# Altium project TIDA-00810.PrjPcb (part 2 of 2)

## Sheet TIDA-00810_ADC1.SchDoc: ADC1
size 431 x 279 mm; Date: Not shown in title block; ApprovedBy: Not shown in title block; CheckedBy: Not shown in title block; Author: Not shown in title block; CompanyName: Not shown in title block; DrawnBy: Sreenivasa; Engineer: Not shown in title block; Organization: Not shown in title block; Address1: Not shown in title block; Address2: Not shown in title block; Address3: Not shown in title block; Address4: Not shown in title block; DocumentNumber: 1; Revision: Use project parameter SCH_Rev; SheetNumber: 7; SheetTotal: 10; PageSetup: Record=PageOptions¦CenterHorizontal=True¦CenterVertical=True¦PrintScale=1.00¦XCorrection=1.00¦YCorrection=1.00¦PrintKind=0¦BorderSize=5000000¦LeftOffset=0¦BottomOffset=0¦Orientation=2¦PaperLength=1000¦PaperWidth=1000¦Scale=100¦PaperSource=15¦PrintQuality=600¦MediaType=1¦DitherType=10¦PaperKind=Letter¦PrintScaleMode=1
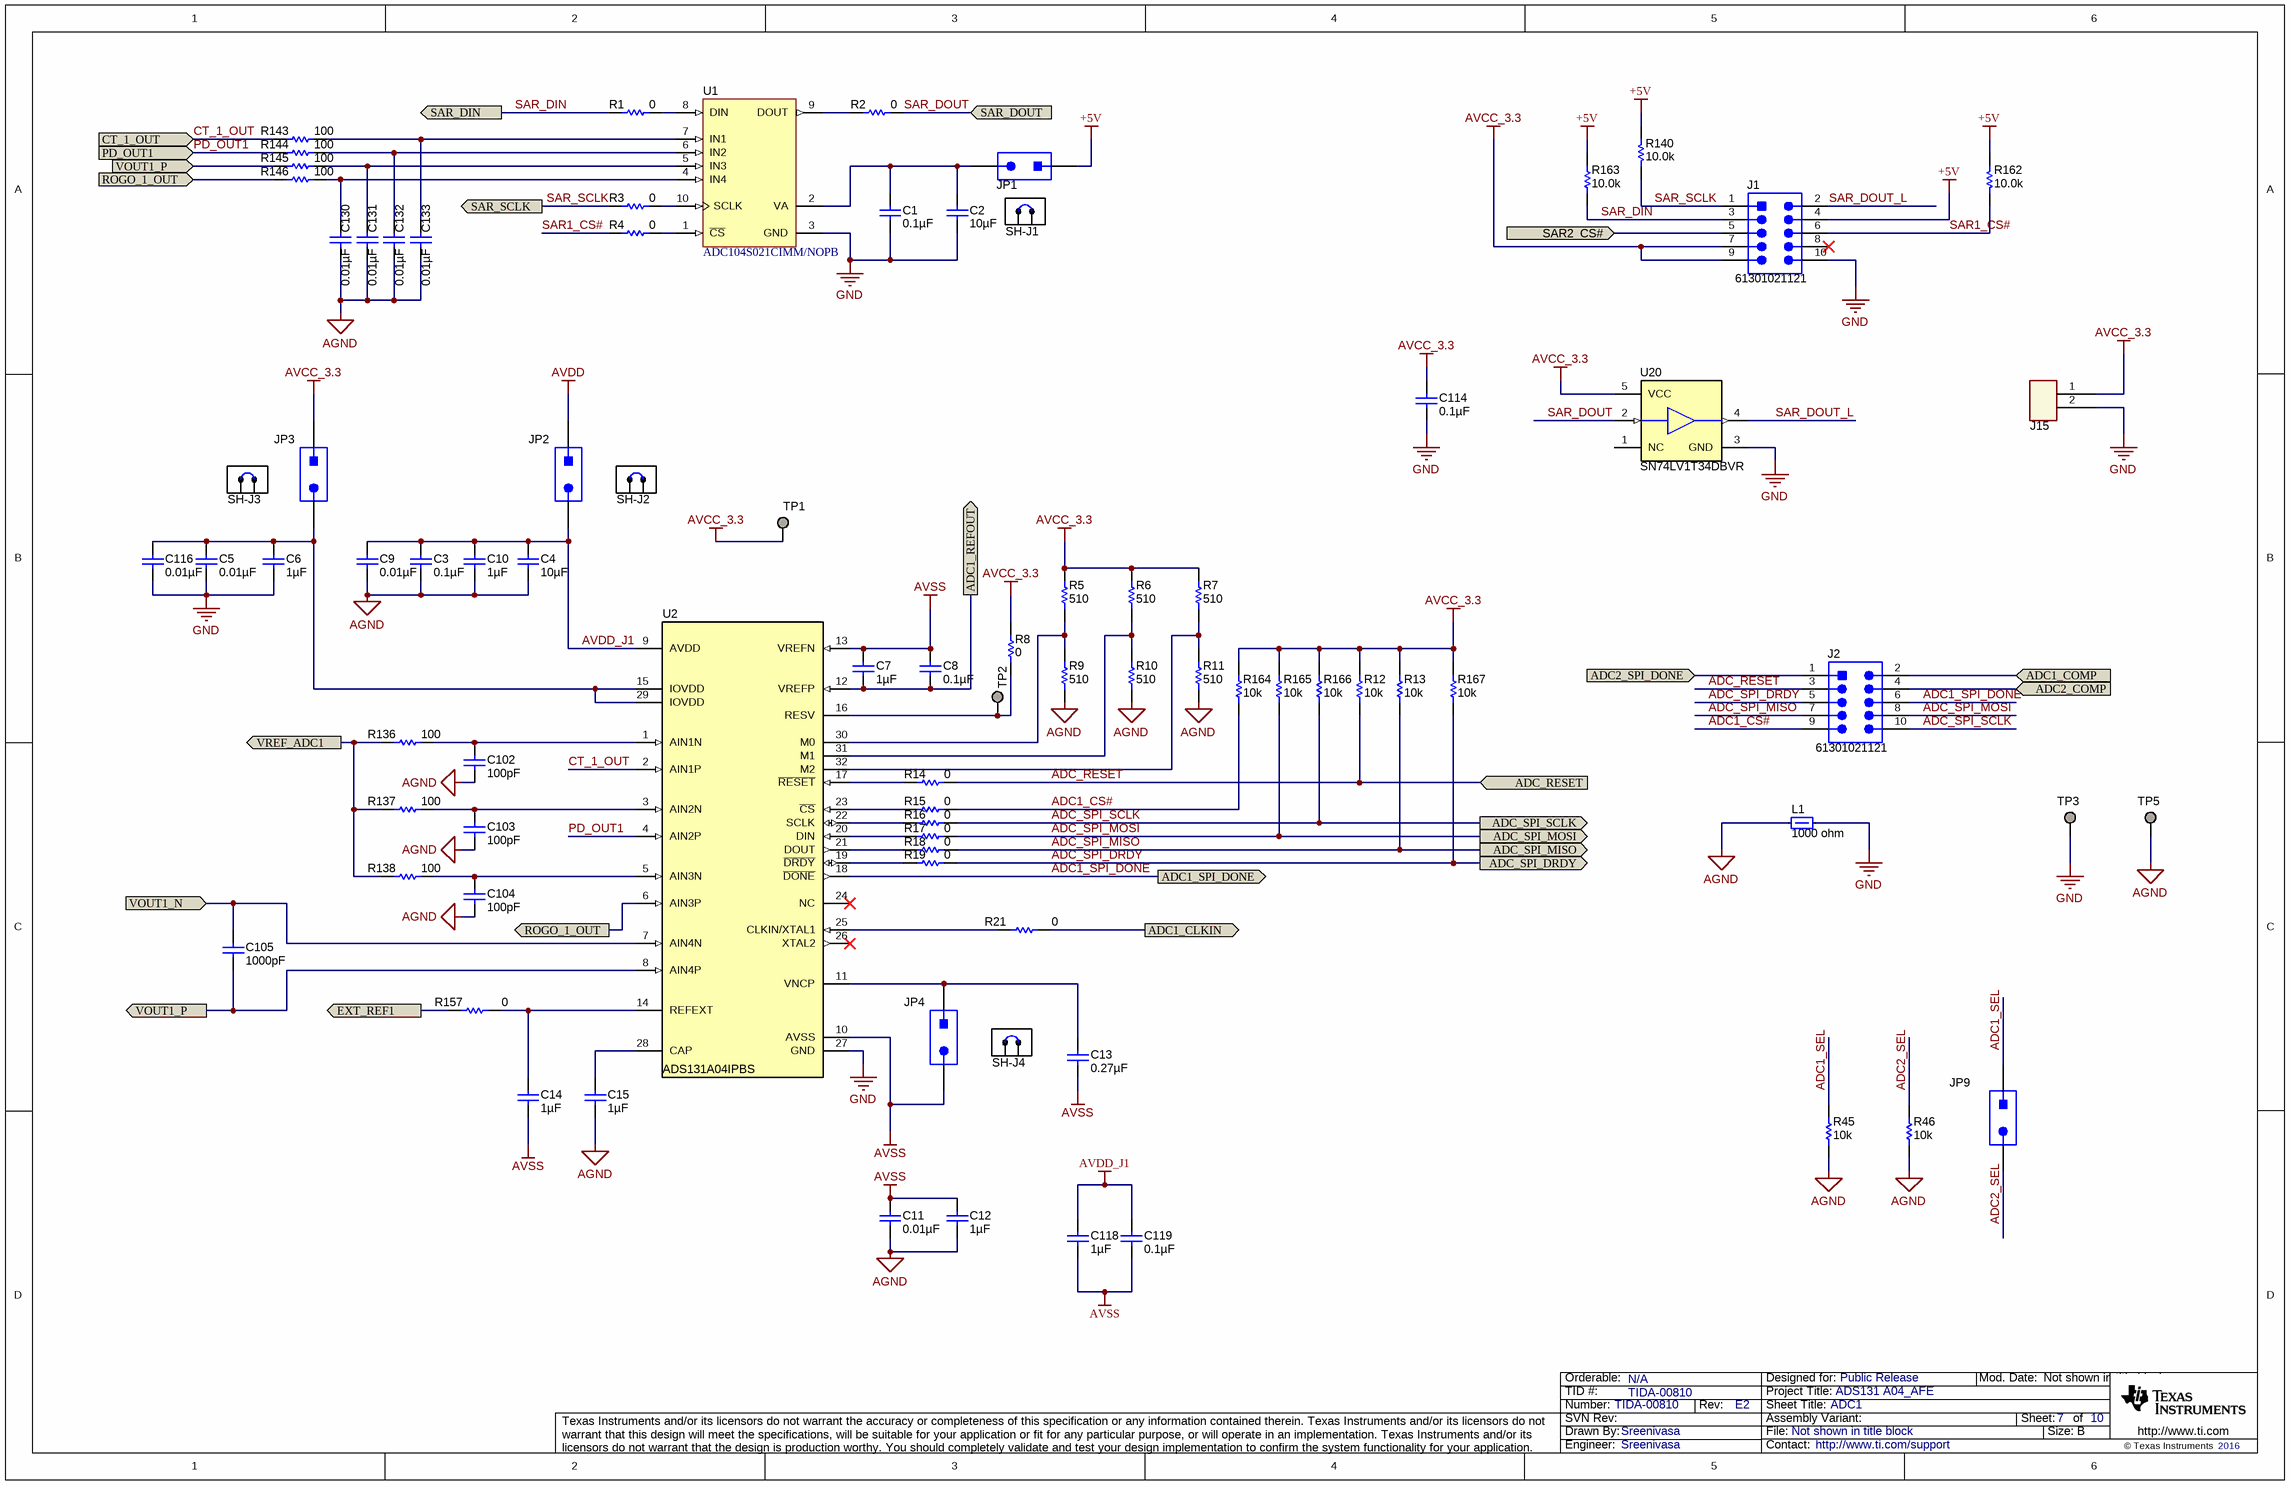
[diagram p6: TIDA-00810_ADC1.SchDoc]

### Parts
C1  ValueDisplayed: 0.1µF  [0603]
C2  ValueDisplayed: 10µF  [1206]  (hidden comment: GMK316AB7106KL)
C3  ValueDisplayed: 0.1µF  [0603]  (hidden comment: 06033C104JAT2A)
C4  ValueDisplayed: 10µF  [0805_HV]  (hidden comment: GRM21BR71A106KE51L)
C5  ValueDisplayed: 0.01µF  [0603]  (hidden comment: 06031C103KAT2A)
C6  ValueDisplayed: 1µF  [0603]  (hidden comment: GRM188R71E105KA12D)
C7  ValueDisplayed: 1µF  [0603]  (hidden comment: GRM188R71E105KA12D)
C8  ValueDisplayed: 0.1µF  [0603]  (hidden comment: 06033C104JAT2A)
C9  ValueDisplayed: 0.01µF  [0603]  (hidden comment: 06031C103KAT2A)
C10  ValueDisplayed: 1µF  [0603]  (hidden comment: GRM188R71E105KA12D)
C11  ValueDisplayed: 0.01µF  [0603]  (hidden comment: 06031C103KAT2A)
C12  ValueDisplayed: 1µF  [0603]  (hidden comment: GRM188R71E105KA12D)
C13  ValueDisplayed: 0.27µF  [0603]  (hidden comment: C0603C274K4RACTU)
C14  ValueDisplayed: 1µF  [0603]  (hidden comment: GRM188R71E105KA12D)
C15  ValueDisplayed: 1µF  [0603]  (hidden comment: GRM188R71E105KA12D)
C102  ValueDisplayed: 100pF  [0603]  (hidden comment: 06033C101KAT2A)
C103  ValueDisplayed: 100pF  [0603]  (hidden comment: 06033C101KAT2A)
C104  ValueDisplayed: 100pF  [0603]  (hidden comment: 06033C101KAT2A)
C105  ValueDisplayed: 1000pF  [0603]  (hidden comment: 06031C102JAT2A)
C114  ValueDisplayed: 0.1µF  [0603]  (hidden comment: 06033C104JAT2A)
C116  ValueDisplayed: 0.01µF  [0603]  (hidden comment: 06031C103KAT2A)
C118  ValueDisplayed: 1µF  [0603]  (hidden comment: GRM188R61E105KA12D)
C119  ValueDisplayed: 0.1µF  [0603]  (hidden comment: GRM188R71H104KA93D)
C130  ValueDisplayed: 0.01µF  [0603]  (hidden comment: 06031C103KAT2A)
C131  ValueDisplayed: 0.01µF  [0603]  (hidden comment: 06031C103KAT2A)
C132  ValueDisplayed: 0.01µF  [0603]  (hidden comment: 06031C103KAT2A)
C133  ValueDisplayed: 0.01µF  [0603]  (hidden comment: 06031C103KAT2A)
J1  61301021121  [WURTH_61301021121]
J2  61301021121  [WURTH_61301021121]
J15  CON-OSTVN02A150  [CN2_MTB_P100_PD80_D1.1_S5.54X6.5_STACK]  (value not drawn)
JP1  5-146280-2  [TSW-102-07-G-S]  (value not drawn)
JP2  5-146280-2  [TSW-102-07-G-S]  (value not drawn)
JP3  5-146280-2  [TSW-102-07-G-S]  (value not drawn)
JP4  5-146280-2  [TSW-102-07-G-S]  (value not drawn)
JP9  5-146280-2  [TSW-102-07-G-S]  (value not drawn)
L1  value 1000 ohm  [MMZ1608_095]  (hidden comment: MMZ1608B102CTA00)
R1  ValueDisplayed: 0  [0603]  (hidden comment: RC0603JR-070RL)
R2  ValueDisplayed: 0  [0603]  (hidden comment: RC0603JR-070RL)
R3  ValueDisplayed: 0  [0603]  (hidden comment: RC0603JR-070RL)
R4  ValueDisplayed: 0  [0603]  (hidden comment: RC0603JR-070RL)
R5  ValueDisplayed: 510  [0603]  (hidden comment: RC0603FR-07510RL)
R6  ValueDisplayed: 510  [0603]  (hidden comment: RC0603FR-07510RL)
R7  ValueDisplayed: 510  [0603]  (hidden comment: RC0603FR-07510RL)
R8  ValueDisplayed: 0  [0603]  (hidden comment: RC0603JR-070RL)
R9  ValueDisplayed: 510  [0603]  (hidden comment: RC0603FR-07510RL)
R10  ValueDisplayed: 510  [0603]  (hidden comment: RC0603FR-07510RL)
R11  ValueDisplayed: 510  [0603]  (hidden comment: RC0603FR-07510RL)
R12  value 10k  [0603]  (hidden comment: CRCW060310K0FKEA)
R13  value 10k  [0603]  (hidden comment: CRCW060310K0FKEA)
R14  ValueDisplayed: 0  [0603]  (hidden comment: RC0603JR-070RL)
R15  ValueDisplayed: 0  [0603]  (hidden comment: RC0603JR-070RL)
R16  ValueDisplayed: 0  [0603]  (hidden comment: RC0603JR-070RL)
R17  ValueDisplayed: 0  [0603]  (hidden comment: RC0603JR-070RL)
R18  ValueDisplayed: 0  [0603]  (hidden comment: RC0603JR-070RL)
R19  ValueDisplayed: 0  [0603]  (hidden comment: RC0603JR-070RL)
R21  ValueDisplayed: 0  [0603]  (hidden comment: ERJ-3GEY0R00V)
R45  value 10k  [0603]  (hidden comment: CRCW060310K0FKEA)
R46  value 10k  [0603]  (hidden comment: CRCW060310K0FKEA)
R136  value 100  [0603]  (hidden comment: CRCW0603100RFKEA)
R137  value 100  [0603]  (hidden comment: CRCW0603100RFKEA)
R138  value 100  [0603]  (hidden comment: CRCW0603100RFKEA)
R140  ValueDisplayed: 10.0k  [0603]  (hidden comment: CRCW060310K0FKEA)
R143  value 100  [0603]  (hidden comment: CRCW0603100RFKEA)
R144  value 100  [0603]  (hidden comment: CRCW0603100RFKEA)
R145  value 100  [0603]  (hidden comment: CRCW0603100RFKEA)
R146  value 100  [0603]  (hidden comment: CRCW0603100RFKEA)
R157  ValueDisplayed: 0  [0603]  (hidden comment: ERJ-3GEY0R00V)
R162  ValueDisplayed: 10.0k  [0603]  (hidden comment: CRCW060310K0FKEA)
R163  ValueDisplayed: 10.0k  [0603]  (hidden comment: CRCW060310K0FKEA)
R164  value 10k  [0603]  (hidden comment: CRCW060310K0FKEA)
R165  value 10k  [0603]  (hidden comment: CRCW060310K0FKEA)
R166  value 10k  [0603]  (hidden comment: CRCW060310K0FKEA)
R167  value 10k  [0603]  (hidden comment: CRCW060310K0FKEA)
SH-J1  881545-2  [TE_881545-2]  (value not drawn)  (mechanical)
SH-J2  881545-2  [TE_881545-2]  (value not drawn)  (mechanical)
SH-J3  881545-2  [TE_881545-2]  (value not drawn)  (mechanical)
SH-J4  881545-2  [TE_881545-2]  (value not drawn)  (mechanical)
TP1  Pogo Pad  [PogoPad]  (value not drawn)  (no BOM)
TP2  Pogo Pad  [PogoPad]  (value not drawn)  (no BOM)
TP3  Suggest using a net name here  [Keystone1573-2]  (value not drawn)
TP5  Suggest using a net name here  [Keystone1573-2]  (value not drawn)
U1  ADC104S021CIMM/NOPB  [MUB10A_N]
U2  ADS131A04IPBS  [PBS0032A_N]
U20  SN74LV1T34DBVR  [DBV0005A_N]

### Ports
ADC1_CLKIN (out), ADC1_COMP (in), ADC1_REFOUT (out), ADC1_SPI_DONE (out), ADC2_COMP (in), ADC2_SPI_DONE (in), ADC_RESET (in), ADC_SPI_DRDY, ADC_SPI_MISO, ADC_SPI_MOSI, ADC_SPI_SCLK, CT_1_OUT (in), EXT_REF1 (out), PD_OUT1 (in), ROGO_1_OUT (in), ROGO_1_OUT (out), SAR2_CS# (in), SAR_DIN, SAR_DOUT, SAR_SCLK, VOUT1_N (in), VOUT1_P (in), VOUT1_P (out), VREF_ADC1

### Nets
+5V: J1.4 JP1.1 R140.2 R162.2 R163.2
AGND: C3.2 C4.2 C9.2 C10.2 C11.2 C12.2 C15.2 C102.2 C103.2 C104.2 C130.2 C131.2 C132.2 C133.2 L1.1 R9.1 R10.1 R11.1 R45.1 R46.1 TP5.1
AVCC_3.3: C114.1 J1.7 J1.9 J15.1 JP3.1 R5.2 R6.2 R7.2 R8.1 R12.2 R13.2 R164.2 R165.2 R166.2 R167.2 TP1.1 U20.5(VCC)
AVDD: JP2.1
AVDD_J1: C3.1 C4.1 C9.1 C10.1 C118.1 C119.1 JP2.2 U2.9(AVDD)
AVSS: C7.1 C8.1 C11.1 C12.1 C13.2 C14.2 C118.2 C119.2 JP4.2 U2.10(AVSS) U2.13(VREFN)
GND: C1.2 C2.2 C5.2 C6.2 C114.2 C116.2 J1.10 J15.2 L1.2 TP3.1 U1.3(GND) U2.27(GND) U20.3(GND)
ADC1_CLKIN: R21.2 ; port ADC1_CLKIN
ADC1_COMP: J2.2 ; port ADC1_COMP
ADC1_CS#: J2.9 R15.1 R164.1
ADC1_REFOUT: C7.2 C8.2 U2.12(VREFP) ; port ADC1_REFOUT
ADC1_SEL: JP9.1 R45.2
ADC1_SPI_DONE: J2.6 U2.18(~{DONE}) ; port ADC1_SPI_DONE
ADC2_COMP: J2.4 ; port ADC2_COMP
ADC2_SEL: JP9.2 R46.2
ADC2_SPI_DONE: J2.1 ; port ADC2_SPI_DONE
ADC_RESET: J2.3 R12.1 R14.1 ; port ADC_RESET
ADC_SPI_DRDY: J2.5 R19.1 R167.1 ; port ADC_SPI_DRDY
ADC_SPI_MISO: J2.7 R13.1 R18.1 ; port ADC_SPI_MISO
ADC_SPI_MOSI: J2.8 R17.1 R165.1 ; port ADC_SPI_MOSI
ADC_SPI_SCLK: J2.10 R16.1 R166.1 ; port ADC_SPI_SCLK
CT_1_OUT: R143.2 U2.2(AIN1P) ; port CT_1_OUT
EXT_REF1: R157.1 ; port EXT_REF1
PD_OUT1: R144.2 U2.4(AIN2P) ; port PD_OUT1
ROGO_1_OUT: R146.2 U2.6(AIN3P) ; port ROGO_1_OUT
SAR1_CS#: J1.6 R4.2 R162.1
SAR2_CS#: J1.5 ; port SAR2_CS#
SAR_DIN: J1.3 R1.2 R163.1 ; port SAR_DIN
SAR_DOUT: R2.1 U20.2(A) ; port SAR_DOUT
SAR_DOUT_L: J1.2 U20.4(Y)
SAR_SCLK: J1.1 R3.2 R140.1 ; port SAR_SCLK
VOUT1_N: C105.1 U2.7(AIN4N) ; port VOUT1_N
VOUT1_P: C105.2 R145.2 U2.8(AIN4P) ; port VOUT1_P
VREF_ADC1: R136.1 R137.1 R138.1 ; port VREF_ADC1
NetC1_1: C1.1 C2.1 JP1.2 U1.2(VA)
NetC5_1: C5.1 C6.1 C116.1 JP3.2 U2.15(IOVDD) U2.29(IOVDD)
NetC13_1: C13.1 JP4.1 U2.11(VNCP)
NetC14_1: C14.1 R157.2 U2.14(REFEXT)
NetC15_1: C15.1 U2.28(CAP)
NetC102_1: C102.1 R136.2 U2.1(AIN1N)
NetC103_1: C103.1 R137.2 U2.3(AIN2N)
NetC104_1: C104.1 R138.2 U2.5(AIN3N)
NetC130_1: C130.1 R146.1 U1.4(IN4)
NetC131_1: C131.1 R145.1 U1.5(IN3)
NetC132_1: C132.1 R144.1 U1.6(IN2)
NetC133_1: C133.1 R143.1 U1.7(IN1)
NetR1_1: R1.1 U1.8(DIN)
NetR2_2: R2.2 U1.9(DOUT)
NetR3_1: R3.1 U1.10(SCLK)
NetR4_1: R4.1 U1.1(~{CS})
NetR5_1: R5.1 R9.2 U2.30(M0)
NetR6_1: R6.1 R10.2 U2.31(M1)
NetR7_1: R7.1 R11.2 U2.32(M2)
NetR8_2: R8.2 TP2.1 U2.16(RESV)
NetR14_2: R14.2 U2.17(~{RESET})
NetR15_2: R15.2 U2.23(~{CS})
NetR16_2: R16.2 U2.22(SCLK)
NetR17_2: R17.2 U2.20(DIN)
NetR18_2: R18.2 U2.21(DOUT)
NetR19_2: R19.2 U2.19(~{DRDY})
NetR21_1: R21.1 U2.25(CLKIN/XTAL1)

Not connected (* = marked no-connect by the designer): J1 8*; U2 24(NC)* 26(XTAL2)*; U20 1(NC)

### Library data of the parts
C1 = 06033C104JAT2A: CAP, CERM, 0.1uF, 25V, +/-5%, X7R, 0603; Manufacturer: AVX; Polarized: N; CompType: Capacitor; U/M: EA; Cap_F: 0.0000001; Tolerance_%: 5; ESR_Ohm: 0.05; Value1: 0.05 ohm; VDC_V: 25; TaMin_C: -55; TaMax_C: 125
C2 = GMK316AB7106KL: CAP, CERM, 10uF, 35V, +/-10%, X7R, 1206; Manufacturer: Taiyo Yuden; Polarized: N; CompType: Capacitor; U/M: EA; Cap_F: 0.00001; Tolerance_%: 10; Value1: Unknown; VDC_V: 35; TaMin_C: -55; TaMax_C: 125
C3 C8 C114 = 06033C104JAT2A: CAP, CERM, 0.1 µF, 25 V, +/- 5%, X7R, 0603; Manufacturer: AVX; Polarized: N; CompType: Capacitor; Value: 0.1uF; U/M: EA; Cap_F: 0.0000001; Tolerance_%: 5; ESR_ohm: 0.05; Value1: 0.05 ohm; VDC_V: 25; Value2: 25V; TaMin_C: -55; TaMax_C: 125; AEC Category: Q200
C4 = GRM21BR71A106KE51L: CAP, CERM, 10 µF, 10 V, +/- 10%, X7R, 0805; Manufacturer: MuRata; Polarized: N; CompType: Capacitor; Value: 10uF; U/M: EA; Cap_F: 0.00001; Tolerance_%: 10; ESR_ohm: 0.003; Value1: 0.003 ohm; Value2: 10V; TaMin_C: -55; TaMax_C: 125; Cap_Case: 0805; AEC Category: Q200
C5 C9 C11 C116 C130-C133 = 06031C103KAT2A: CAP, CERM, 0.01 µF, 100 V, +/- 10%, X7R, 0603; Manufacturer: AVX; Polarized: N; CompType: Capacitor; Value: 0.01uF; U/M: EA; Cap_F: 0.00000001; Tolerance_%: 10; ESR_ohm: 0.098; Value1: 0.098 ohm; VDC_V: 100; Value2: 100V; TaMin_C: -55; TaMax_C: 125; AEC Category: Q200
C6 C7 C10 C12 C14 C15 = GRM188R71E105KA12D: CAP, CERM, 1 µF, 25 V, +/- 10%, X7R, 0603; Manufacturer: MuRata; Polarized: N; CompType: Capacitor; Value: 1uF; U/M: EA; Cap_F: 0.000001; Tolerance_%: 10; Value1: Unknown; VDC_V: 25; Value2: 25V; TaMin_C: -55; TaMax_C: 125; AEC Category: Q200
C13 = C0603C274K4RACTU: CAP, CERM, 0.27 µF, 16 V, +/- 10%, X7R, 0603; Manufacturer: Kemet; Polarized: N; CompType: Capacitor; Value: 0.27uF; U/M: EA; Cap_F: 0.00000027; Tolerance_%: 10; Value1: Unknown; VDC_V: 16; Value2: 16V; TaMin_C: -55; TaMax_C: 125; AEC Category: Q200
C102-C104 = 06033C101KAT2A: CAP, CERM, 100 pF, 25 V, +/- 10%, X7R, 0603; Manufacturer: AVX; Polarized: N; CompType: Capacitor; Value: 100pF; U/M: EA; Cap_F: 0.0000000001; Tolerance_%: 10; Value1: Unknown; VDC_V: 25; Value2: 25V; TaMin_C: -55; TaMax_C: 125; AEC Category: Q200
C105 = 06031C102JAT2A: CAP, CERM, 1000 pF, 100 V, +/- 5%, X7R, 0603; Manufacturer: AVX; Polarized: N; CompType: Capacitor; Value: 1000pF; U/M: EA; Cap_F: 0.000000001; Tolerance_%: 5; ESR_ohm: 0.276; Value1: 0.276 ohm; VDC_V: 100; Value2: 100V; TaMin_C: -55; TaMax_C: 125; AEC Category: Q200
C118 = GRM188R61E105KA12D: CAP, CERM, 1 µF, 25 V, +/- 10%, X5R, 0603; Manufacturer: MuRata; Polarized: N; CompType: Capacitor; Value: 1uF; U/M: EA; Cap_F: 0.000001; Tolerance_%: 10; Value1: Unknown; VDC_V: 25; Value2: 25V; TaMin_C: -55; TaMax_C: 85; AEC Category: Q200
C119 = GRM188R71H104KA93D: CAP, CERM, 0.1 µF, 50 V, +/- 10%, X7R, 0603; Manufacturer: MuRata; Polarized: N; CompType: Capacitor; Value: 0.1uF; U/M: EA; Cap_F: 0.0000001; Tolerance_%: 10; Value1: Unknown; VDC_V: 50; Value2: 50V; TaMin_C: -55; TaMax_C: 125; AEC Category: Q200
J1 J2 = 61301021121: Header, 2.54 mm, 5x2, Gold, TH; Manufacturer: Wurth Elektronik; SymbolCreator: a0412235
J15 = CON-OSTVN02A150: Terminal Block, 4x1, 2.54mm, TH; Manufacturer: On Shore Technology Inc; SymbolCreator: x0120606
JP1-JP4 JP9 = TSW-102-07-G-S: Header, 100mil, 2x1, Gold, TH; Manufacturer: TE Connectivity; SymbolCreator: a0412235; U/M: EA
L1 = MMZ1608B102CTA00: Ferrite Bead, 1000 ohm @ 100 MHz, 0.3 A, 0603; Manufacturer: TDK; Imax_A: 0.3; DCR_ohm: 0.6; Value1: 0.6 ohm; Value2: 0.3A; ZTyp@100MHz_Ohm: 1000
R1-R4 R8 R14-R19 = RC0603JR-070RL: RES, 0, 5%, 0.1 W, 0603; Manufacturer: Yageo America; CompType: Resistor; Value: 0; Value_Code: 0000; Tolerance_%: 5; Power_W: 0.1; Value2: 0.1W; VDC_V: 50; TempCo: 200 ppm/C; EIA_Code: E24; U/M: EA; AEC Category: Q200
R5-R7 R9-R11 = RC0603FR-07510RL: RES, 510, 1%, 0.1 W, 0603; Manufacturer: Yageo America; CompType: Resistor; Value: 510; Value_Code: 510R; Tolerance_%: 1; Power_W: 0.1; Value2: 0.1W; VDC_V: 150; TempCo: 200 ppm/C; U/M: EA; AEC Category: Q200
R12 R13 R45 R46 R164-R167 = RNCF0603TKY10K0: RES, 10.0k ohm, 1%, 0.1W, 0603; Manufacturer: Stackpole Electronics Inc; CompType: Resistor; Res_ohm: 10000; Value_Code: 10k0; Tolerance_%: 0.01; Value1: 0.01%; Power_W: 0.063; Value2: 0.063W; VDC_V: 50; TempCo: 5 ppm/C; U/M: EA
R21 R157 = ERJ-3GEY0R00V: RES, 0, 5%, 0.1 W, 0603; Manufacturer: Panasonic; CompType: Resistor; Value: 0; Value_Code: 0000; Tolerance_%: 5; Power_W: 0.1; Value2: 0.1W; VDC_V: 50; TempCo: 600 ppm/C; EIA_Code: E24; U/M: EA; AEC Category: Q200
R136-R138 R143-R146 = CRCW0603100RFKEA: RES, 100 ohm, 1%, 0.1W, 0603; Manufacturer: Vishay-Dale; CompType: Resistor; Value_Code: 100R; Tolerance_%: 1; Power_W: 0.1; VDC_V: 75; TempCo: 100 ppm/C; EIA_Code: E96; U/M: EA
R140 R162 R163 = CRCW060310K0FKEA: RES, 10.0 k, 1%, 0.1 W, 0603; Manufacturer: Vishay-Dale; CompType: Resistor; Value: 10.0k; Res_ohm: 10000; Value_Code: 10k0; Tolerance_%: 1; Power_W: 0.1; Value2: 0.1W; VDC_V: 75; TempCo: 100 ppm/C; EIA_Code: E96; U/M: EA; AEC Category: Q200
SH-J1-SH-J4 = 881545-2: Shunt, 100mil, Gold plated, Black; Manufacturer: TE Connectivity
TP1 TP2 = PogoPad: Pad for Pogo Pin Connector; SymbolCreator: codlsc
TP3 TP5 = 1573-2: Terminal, Turret, TH, Double; Manufacturer: Keystone; CompType: Turret Terminal; U/M: EA
U1 = ADC104S021CIMM/NOPB: 4 Channel, 50 kSPS to 200 kSPS, 10-Bit A/D Converter, 10-pin Mini SOIC, Pb-Free; Manufacturer: Texas Instruments; PackageTopMarking: ZXTT*X20C; PowerWise: Y; CompType: ADC IC
U2 = ADS131A04IPBS: Four Channel Analog Front-End for Power Monitoring, Control, and Protection, PBS0032A; Alternate Manufacturer: Texas Instruments; SymbolCreator: a0411947; CompType: IC; U/M: EA
U20 = SN74LV1T34DBVR: Single Power Supply Single Buffer GATE CMOS Logic Level Shifter, DBV0005A; Manufacturer: Texas Instruments; SymbolCreator: Altium; CompType: IC; U/M: EA

## Sheet TIDA-00810_ADC2.SchDoc: ADC2
size 431 x 279 mm; Date: Not shown in title block; ApprovedBy: Not shown in title block; CheckedBy: Not shown in title block; Author: Not shown in title block; CompanyName: Not shown in title block; DrawnBy: Sreenivasa; Engineer: Not shown in title block; Organization: Not shown in title block; Address1: Not shown in title block; Address2: Not shown in title block; Address3: Not shown in title block; Address4: Not shown in title block; DocumentNumber: 1; Revision: Use project parameter SCH_Rev; SheetNumber: 8; SheetTotal: 10; PageSetup: Record=PageOptions¦CenterHorizontal=True¦CenterVertical=True¦PrintScale=1.00¦XCorrection=1.00¦YCorrection=1.00¦PrintKind=0¦BorderSize=5000000¦LeftOffset=0¦BottomOffset=0¦Orientation=2¦PaperLength=1000¦PaperWidth=1000¦Scale=100¦PaperSource=15¦PrintQuality=600¦MediaType=1¦DitherType=10¦PaperKind=Letter¦PrintScaleMode=1
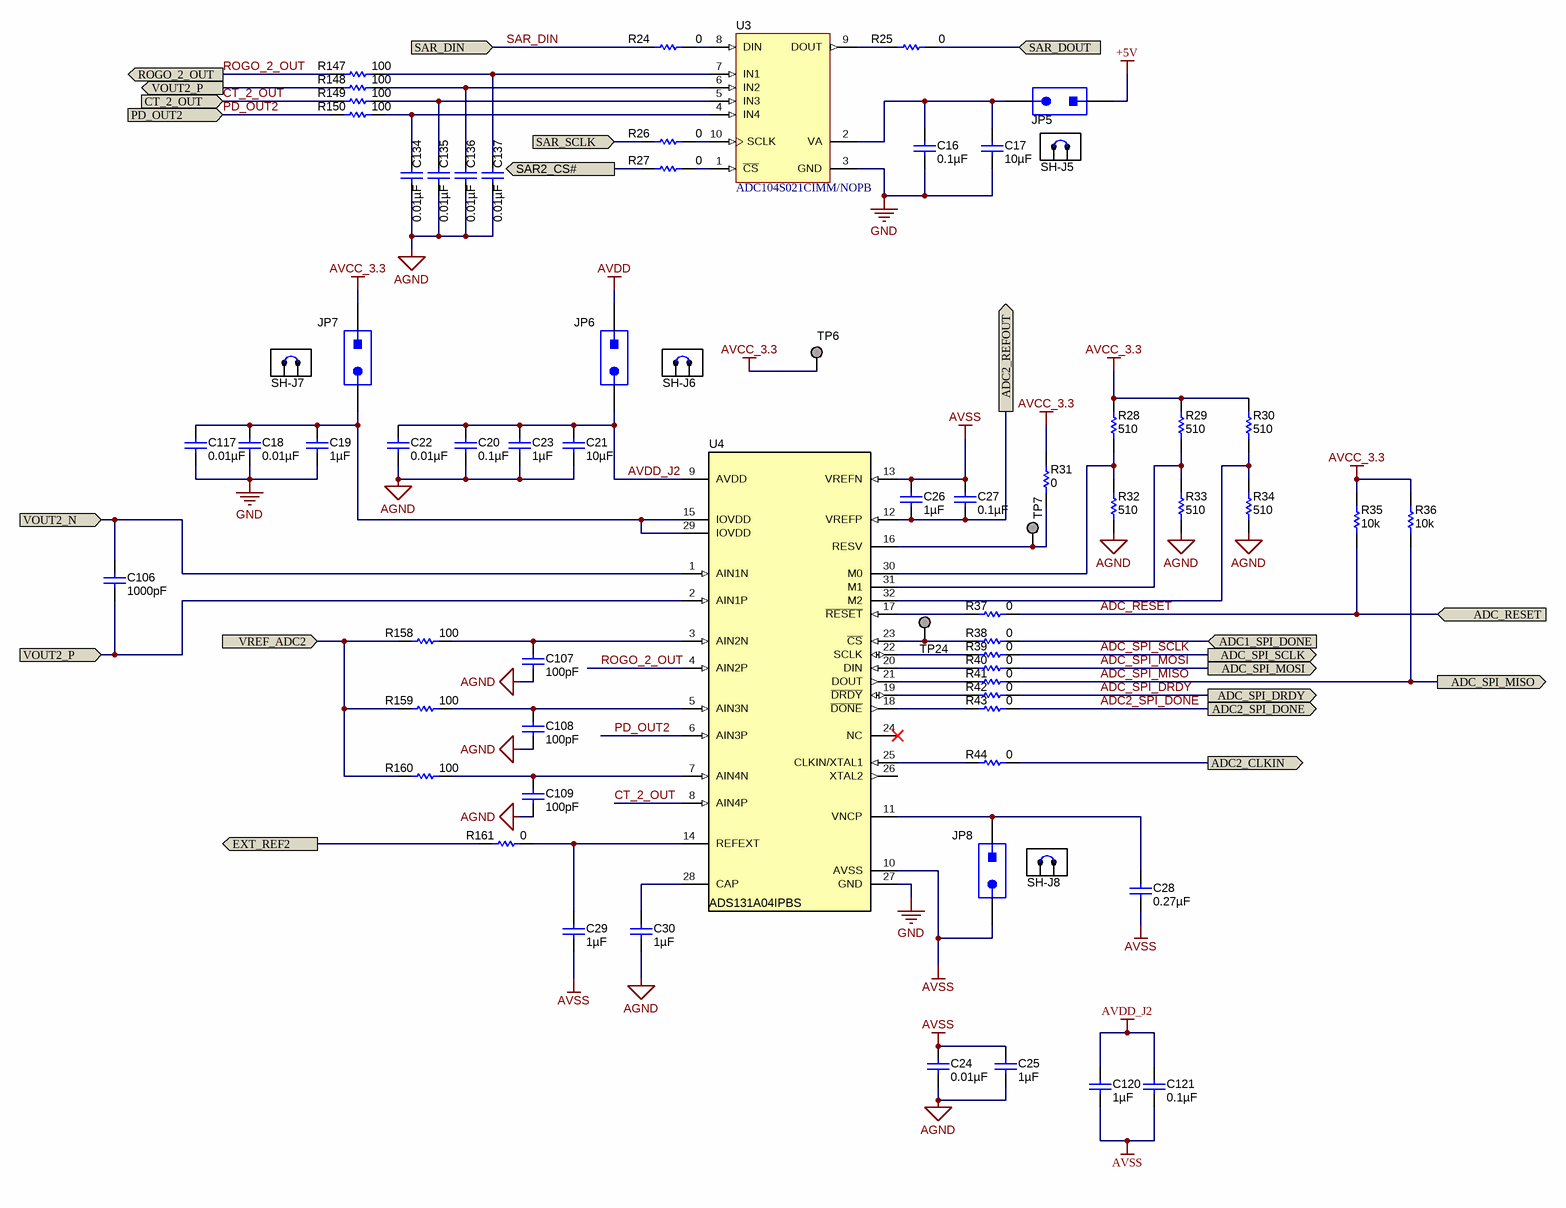
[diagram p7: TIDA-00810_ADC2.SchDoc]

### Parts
C16  ValueDisplayed: 0.1µF  [0603]
C17  ValueDisplayed: 10µF  [1206]  (hidden comment: GMK316AB7106KL)
C18  ValueDisplayed: 0.01µF  [0603]  (hidden comment: 06031C103KAT2A)
C19  ValueDisplayed: 1µF  [0603]  (hidden comment: GRM188R71E105KA12D)
C20  ValueDisplayed: 0.1µF  [0603]  (hidden comment: 06033C104JAT2A)
C21  ValueDisplayed: 10µF  [0805_HV]  (hidden comment: GRM21BR71A106KE51L)
C22  ValueDisplayed: 0.01µF  [0603]  (hidden comment: 06031C103KAT2A)
C23  ValueDisplayed: 1µF  [0603]  (hidden comment: GRM188R71E105KA12D)
C24  ValueDisplayed: 0.01µF  [0603]  (hidden comment: 06031C103KAT2A)
C25  ValueDisplayed: 1µF  [0603]  (hidden comment: GRM188R71E105KA12D)
C26  ValueDisplayed: 1µF  [0603]  (hidden comment: GRM188R71E105KA12D)
C27  ValueDisplayed: 0.1µF  [0603]  (hidden comment: 06033C104JAT2A)
C28  ValueDisplayed: 0.27µF  [0603]  (hidden comment: C0603C274K4RACTU)
C29  ValueDisplayed: 1µF  [0603]  (hidden comment: GRM188R71E105KA12D)
C30  ValueDisplayed: 1µF  [0603]  (hidden comment: GRM188R71E105KA12D)
C106  ValueDisplayed: 1000pF  [0603]  (hidden comment: 06031C102JAT2A)
C107  ValueDisplayed: 100pF  [0603]  (hidden comment: 06033C101KAT2A)
C108  ValueDisplayed: 100pF  [0603]  (hidden comment: 06033C101KAT2A)
C109  ValueDisplayed: 100pF  [0603]  (hidden comment: 06033C101KAT2A)
C117  ValueDisplayed: 0.01µF  [0603]  (hidden comment: 06031C103KAT2A)
C120  ValueDisplayed: 1µF  [0603]  (hidden comment: GRM188R61E105KA12D)
C121  ValueDisplayed: 0.1µF  [0603]  (hidden comment: GRM188R71H104KA93D)
C134  ValueDisplayed: 0.01µF  [0603]  (hidden comment: 06031C103KAT2A)
C135  ValueDisplayed: 0.01µF  [0603]  (hidden comment: 06031C103KAT2A)
C136  ValueDisplayed: 0.01µF  [0603]  (hidden comment: 06031C103KAT2A)
C137  ValueDisplayed: 0.01µF  [0603]  (hidden comment: 06031C103KAT2A)
JP5  5-146280-2  [TSW-102-07-G-S]  (value not drawn)
JP6  5-146280-2  [TSW-102-07-G-S]  (value not drawn)
JP7  5-146280-2  [TSW-102-07-G-S]  (value not drawn)
JP8  5-146280-2  [TSW-102-07-G-S]  (value not drawn)
R24  ValueDisplayed: 0  [0603]  (hidden comment: RC0603JR-070RL)
R25  ValueDisplayed: 0  [0603]  (hidden comment: RC0603JR-070RL)
R26  ValueDisplayed: 0  [0603]  (hidden comment: RC0603JR-070RL)
R27  ValueDisplayed: 0  [0603]  (hidden comment: RC0603JR-070RL)
R28  ValueDisplayed: 510  [0603]  (hidden comment: RC0603FR-07510RL)
R29  ValueDisplayed: 510  [0603]  (hidden comment: RC0603FR-07510RL)
R30  ValueDisplayed: 510  [0603]  (hidden comment: RC0603FR-07510RL)
R31  ValueDisplayed: 0  [0603]  (hidden comment: RC0603JR-070RL)
R32  ValueDisplayed: 510  [0603]  (hidden comment: RC0603FR-07510RL)
R33  ValueDisplayed: 510  [0603]  (hidden comment: RC0603FR-07510RL)
R34  ValueDisplayed: 510  [0603]  (hidden comment: RC0603FR-07510RL)
R35  value 10k  [0603]  (hidden comment: CRCW060310K0FKEA)
R36  value 10k  [0603]  (hidden comment: CRCW060310K0FKEA)
R37  ValueDisplayed: 0  [0603]  (hidden comment: RC0603JR-070RL)
R38  ValueDisplayed: 0  [0603]  (hidden comment: RC0603JR-070RL)
R39  ValueDisplayed: 0  [0603]  (hidden comment: RC0603JR-070RL)
R40  ValueDisplayed: 0  [0603]  (hidden comment: RC0603JR-070RL)
R41  ValueDisplayed: 0  [0603]  (hidden comment: RC0603JR-070RL)
R42  ValueDisplayed: 0  [0603]  (hidden comment: RC0603JR-070RL)
R43  ValueDisplayed: 0  [0603]  (hidden comment: RC0603JR-070RL)
R44  ValueDisplayed: 0  [0603]  (hidden comment: ERJ-3GEY0R00V)
R147  value 100  [0603]  (hidden comment: CRCW0603100RFKEA)
R148  value 100  [0603]  (hidden comment: CRCW0603100RFKEA)
R149  value 100  [0603]  (hidden comment: CRCW0603100RFKEA)
R150  value 100  [0603]  (hidden comment: CRCW0603100RFKEA)
R158  value 100  [0603]  (hidden comment: CRCW0603100RFKEA)
R159  value 100  [0603]  (hidden comment: CRCW0603100RFKEA)
R160  value 100  [0603]  (hidden comment: CRCW0603100RFKEA)
R161  ValueDisplayed: 0  [0603]  (hidden comment: ERJ-3GEY0R00V)
SH-J5  881545-2  [TE_881545-2]  (value not drawn)  (mechanical)
SH-J6  881545-2  [TE_881545-2]  (value not drawn)  (mechanical)
SH-J7  881545-2  [TE_881545-2]  (value not drawn)  (mechanical)
SH-J8  881545-2  [TE_881545-2]  (value not drawn)  (mechanical)
TP6  Pogo Pad  [PogoPad]  (value not drawn)  (no BOM)
TP7  Pogo Pad  [PogoPad]  (value not drawn)  (no BOM)
TP24  Pogo Pad  [PogoPad]  (value not drawn)  (no BOM)
U3  ADC104S021CIMM/NOPB  [MUB10A_N]
U4  ADS131A04IPBS  [PBS0032A_N]

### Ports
ADC1_SPI_DONE (in), ADC2_CLKIN (out), ADC2_REFOUT (out), ADC2_SPI_DONE (out), ADC_RESET (in), ADC_SPI_DRDY, ADC_SPI_MISO, ADC_SPI_MOSI, ADC_SPI_SCLK, CT_2_OUT (in), EXT_REF2 (out), PD_OUT2 (in), ROGO_2_OUT (out), SAR2_CS# (out), SAR_DIN (in), SAR_DOUT, SAR_SCLK (in), VOUT2_N (in), VOUT2_P (in), VOUT2_P (out), VREF_ADC2

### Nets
+5V: JP5.1
AGND: C20.2 C21.2 C22.2 C23.2 C24.2 C25.2 C30.2 C107.2 C108.2 C109.2 C134.2 C135.2 C136.2 C137.2 R32.1 R33.1 R34.1
AVCC_3.3: JP7.1 R28.2 R29.2 R30.2 R31.1 R35.2 R36.2 TP6.1
AVDD: JP6.1
AVDD_J2: C20.1 C21.1 C22.1 C23.1 C120.1 C121.1 JP6.2 U4.9(AVDD)
AVSS: C24.1 C25.1 C26.1 C27.1 C28.2 C29.2 C120.2 C121.2 JP8.2 U4.10(AVSS) U4.13(VREFN)
GND: C16.2 C17.2 C18.2 C19.2 C117.2 U3.3(GND) U4.27(GND)
ADC1_SPI_DONE: R38.1 ; port ADC1_SPI_DONE
ADC2_CLKIN: R44.2 ; port ADC2_CLKIN
ADC2_REFOUT: C26.2 C27.2 U4.12(VREFP) ; port ADC2_REFOUT
ADC2_SPI_DONE: R43.1 ; port ADC2_SPI_DONE
ADC_RESET: R35.1 R37.1 ; port ADC_RESET
ADC_SPI_DRDY: R42.1 ; port ADC_SPI_DRDY
ADC_SPI_MISO: R36.1 R41.1 ; port ADC_SPI_MISO
ADC_SPI_MOSI: R40.1 ; port ADC_SPI_MOSI
ADC_SPI_SCLK: R39.1 ; port ADC_SPI_SCLK
CT_2_OUT: R149.2 U4.8(AIN4P) ; port CT_2_OUT
EXT_REF2: R161.1 ; port EXT_REF2
PD_OUT2: R150.2 U4.6(AIN3P) ; port PD_OUT2
ROGO_2_OUT: R147.2 U4.4(AIN2P) ; port ROGO_2_OUT
SAR2_CS#: R27.2 ; port SAR2_CS#
SAR_DIN: R24.2 ; port SAR_DIN
SAR_DOUT: R25.1 ; port SAR_DOUT
SAR_SCLK: R26.2 ; port SAR_SCLK
VOUT2_N: C106.1 U4.1(AIN1N) ; port VOUT2_N
VOUT2_P: C106.2 R148.2 U4.2(AIN1P) ; port VOUT2_P
VREF_ADC2: R158.1 R159.1 R160.1 ; port VREF_ADC2
NetC16_1: C16.1 C17.1 JP5.2 U3.2(VA)
NetC18_1: C18.1 C19.1 C117.1 JP7.2 U4.15(IOVDD) U4.29(IOVDD)
NetC28_1: C28.1 JP8.1 U4.11(VNCP)
NetC29_1: C29.1 R161.2 U4.14(REFEXT)
NetC30_1: C30.1 U4.28(CAP)
NetC107_1: C107.1 R158.2 U4.3(AIN2N)
NetC108_1: C108.1 R159.2 U4.5(AIN3N)
NetC109_1: C109.1 R160.2 U4.7(AIN4N)
NetC134_1: C134.1 R150.1 U3.4(IN4)
NetC135_1: C135.1 R149.1 U3.5(IN3)
NetC136_1: C136.1 R148.1 U3.6(IN2)
NetC137_1: C137.1 R147.1 U3.7(IN1)
NetR24_1: R24.1 U3.8(DIN)
NetR25_2: R25.2 U3.9(DOUT)
NetR26_1: R26.1 U3.10(SCLK)
NetR27_1: R27.1 U3.1(~{CS})
NetR28_1: R28.1 R32.2 U4.30(M0)
NetR29_1: R29.1 R33.2 U4.31(M1)
NetR30_1: R30.1 R34.2 U4.32(M2)
NetR31_2: R31.2 TP7.1 U4.16(RESV)
NetR37_2: R37.2 U4.17(~{RESET})
NetR38_2: R38.2 TP24.1 U4.23(~{CS})
NetR39_2: R39.2 U4.22(SCLK)
NetR40_2: R40.2 U4.20(DIN)
NetR41_2: R41.2 U4.21(DOUT)
NetR42_2: R42.2 U4.19(~{DRDY})
NetR43_2: R43.2 U4.18(~{DONE})
NetR44_1: R44.1 U4.25(CLKIN/XTAL1)

Not connected (* = marked no-connect by the designer): U4 24(NC)* 26(XTAL2)

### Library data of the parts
C16 = 06033C104JAT2A: as C1 on sheet TIDA-00810_ADC1
C17 = GMK316AB7106KL: as C2 on sheet TIDA-00810_ADC1
C18 C22 C24 C117 C134-C137 = 06031C103KAT2A: as C5 on sheet TIDA-00810_ADC1
C19 C23 C25 C26 C29 C30 = GRM188R71E105KA12D: as C6 on sheet TIDA-00810_ADC1
C20 C27 = 06033C104JAT2A: as C3 on sheet TIDA-00810_ADC1
C21 = GRM21BR71A106KE51L: as C4 on sheet TIDA-00810_ADC1
C28 = C0603C274K4RACTU: as C13 on sheet TIDA-00810_ADC1
C106 = 06031C102JAT2A: as C105 on sheet TIDA-00810_ADC1
C107-C109 = 06033C101KAT2A: as C102-C104 on sheet TIDA-00810_ADC1
C120 = GRM188R61E105KA12D: as C118 on sheet TIDA-00810_ADC1
C121 = GRM188R71H104KA93D: as C119 on sheet TIDA-00810_ADC1
JP5-JP8 = TSW-102-07-G-S: as JP1 on sheet TIDA-00810_ADC1
R24-R27 R31 R37-R43 = RC0603JR-070RL: as R1-R4 on sheet TIDA-00810_ADC1
R28-R30 R32-R34 = RC0603FR-07510RL: as R5 on sheet TIDA-00810_ADC1
R35 R36 = RNCF0603TKY10K0: as R12 on sheet TIDA-00810_ADC1
R44 R161 = ERJ-3GEY0R00V: as R21 on sheet TIDA-00810_ADC1
R147-R150 R158-R160 = CRCW0603100RFKEA: as R136-R138 on sheet TIDA-00810_ADC1
SH-J5-SH-J8 = 881545-2: as SH-J1-SH-J4 on sheet TIDA-00810_ADC1
TP6 TP7 TP24 = PogoPad: as TP1 on sheet TIDA-00810_ADC1
U3 = ADC104S021CIMM/NOPB: as U1 on sheet TIDA-00810_ADC1
U4 = ADS131A04IPBS: as U2 on sheet TIDA-00810_ADC1

## Sheet TIDA-00810_Buffer.SchDoc: Buffer
size 431 x 279 mm; Date: Not shown in title block; ApprovedBy: Not shown in title block; CheckedBy: Not shown in title block; Author: Not shown in title block; CompanyName: Not shown in title block; DrawnBy: Sreenivasa; Engineer: Not shown in title block; Organization: Not shown in title block; Address1: Not shown in title block; Address2: Not shown in title block; Address3: Not shown in title block; Address4: Not shown in title block; DocumentNumber: 1; Revision: Use project parameter SCH_Rev; SheetNumber: 9; SheetTotal: 10; PageSetup: Record=PageOptions¦CenterHorizontal=True¦CenterVertical=True¦PrintScale=1.00¦XCorrection=1.00¦YCorrection=1.00¦PrintKind=0¦BorderSize=5000000¦LeftOffset=0¦BottomOffset=0¦Orientation=2¦PaperLength=1000¦PaperWidth=1000¦Scale=100¦PaperSource=15¦PrintQuality=600¦MediaType=1¦DitherType=10¦PaperKind=Letter¦PrintScaleMode=1
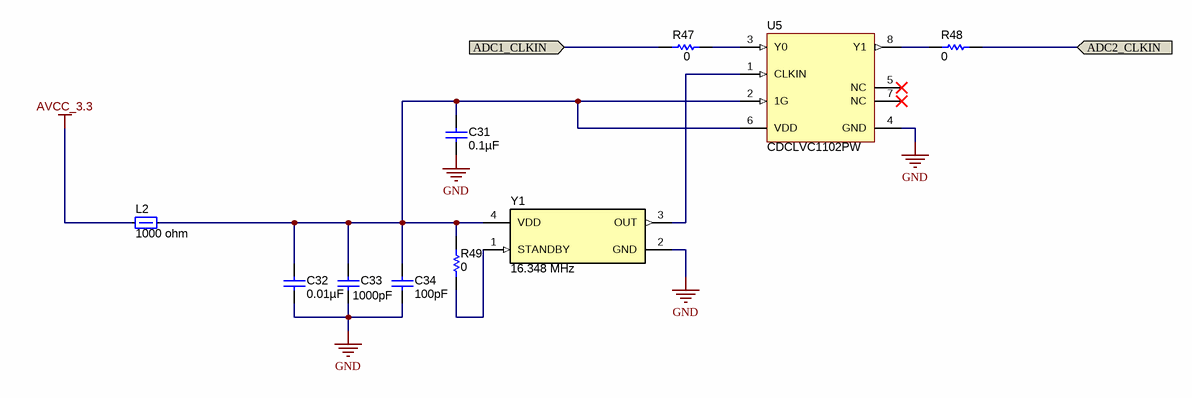
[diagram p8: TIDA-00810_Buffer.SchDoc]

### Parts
C31  ValueDisplayed: 0.1µF  [0603]  (hidden comment: C0603C104K4RACTU)
C32  ValueDisplayed: 0.01µF  [0402]  (hidden comment: GCM155R71H103KA55D)
C33  ValueDisplayed: 1000pF  [0402]  (hidden comment: GRM155R61E102KA01D)
C34  ValueDisplayed: 100pF  [0402]  (hidden comment: CC0402KRX7R9BB101)
L2  value 1000 ohm  [MMZ1608_095]  (hidden comment: MMZ1608B102CTA00)
R47  value 0  [0603]  (hidden comment: CRCW06030000Z0EA)
R48  value 0  [0603]  (hidden comment: CRCW06030000Z0EA)
R49  value 0  [0603]  (hidden comment: CRCW06030000Z0EA)
U5  CDCLVC1102PW  [PW0008A_N]
Y1  Frequency: 16.348 MHz  [Epson_SG-210]  (hidden comment: SG-210STF 16.3480ML)

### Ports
ADC1_CLKIN (in), ADC2_CLKIN (in)

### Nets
AVCC_3.3: L2.1
GND: C31.2 C32.2 C33.2 C34.2 U5.4(GND) Y1.2(GND)
ADC1_CLKIN: R47.1 ; port ADC1_CLKIN
ADC2_CLKIN: R48.1 ; port ADC2_CLKIN
NetC31_1: C31.1 C32.1 C33.1 C34.1 L2.2 R49.1 U5.2(1G) U5.6(VDD) Y1.4(VDD)
NetR47_2: R47.2 U5.3(Y0)
NetR48_2: R48.2 U5.8(Y1)
NetR49_2: R49.2 Y1.1(STANDBY)
NetU5_1: U5.1(CLKIN) Y1.3(OUT)

Not connected (* = marked no-connect by the designer): U5 5(NC)* 7(NC)*

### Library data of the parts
C31 = C0603C104K4RACTU: CAP, CERM, 0.1uF, 16V, +/-10%, X7R, 0603; Manufacturer: Kemet; Polarized: N; CompType: Capacitor; U/M: EA; Cap_F: 0.0000001; Tolerance_%: 10; Value1: Unknown; VDC_V: 16; TaMin_C: -55; TaMax_C: 125
C32 = GCM155R71H103KA55D: CAP, CERM, 0.01uF, 50V, +/-10%, C0G/NP0, 0402; Manufacturer: MuRata; Polarized: N; CompType: Capacitor; U/M: EA; Cap_F: 0.00000001; Tolerance_%: 10; Value1: Unknown; VDC_V: 50; TaMin_C: -55; TaMax_C: 125
C33 = GRM155R61E102KA01D: CAP, CERM, 1000pF, 25V, +/-10%, X5R, 0402; Manufacturer: MuRata; Polarized: N; CompType: Capacitor; U/M: EA; Cap_F: 0.000000001; Tolerance_%: 10; Value1: Unknown; VDC_V: 25; TaMin_C: -55; TaMax_C: 85
C34 = CC0402KRX7R9BB101: CAP, CERM, 100pF, 50V, +/-10%, X7R, 0402; Manufacturer: Yageo America; Polarized: N; CompType: Capacitor; U/M: EA; Cap_F: 0.0000000001; Tolerance_%: 10; Value1: Unknown; VDC_V: 50; TaMin_C: -55; TaMax_C: 125
L2 = MMZ1608B102CTA00: as L1 on sheet TIDA-00810_ADC1
R47-R49 = CRCW06030000Z0EA: RES, 0 ohm, 5%, 0.1W, 0603; Manufacturer: Vishay-Dale; CompType: Resistor; Value_Code: 0000; Tolerance_%: 5; Power_W: 0.1; VDC_V: 75; TempCo: 200 ppm/C; EIA_Code: E24; U/M: EA
U5 = CDCLVC1102PW: 3.3 V and 2.5 V LVCMOS High-Performance Clock Buffer Family, PW0008A; Alternate Manufacturer: None; Manufacturer: Texas Instruments; SymbolCreator: a0799628; CompType: IC; U/M: EA
Y1 = SG-210STF 13.5600ML: Oscillator, 13.56MHz, 1.6 to 3.6 V, SMD; Manufacturer: Epson; SymbolCreator: Altium; U/M: EA; TaMin_C: -40; TaMax_C: 85; Frequency Stability: ±50ppm

## Sheet TIDA-00810_EVM_Hardware.SchDoc: EVM_Hardware
size 431 x 279 mm; Date: Not shown in title block; ApprovedBy: Not shown in title block; CheckedBy: Not shown in title block; Author: Not shown in title block; CompanyName: Not shown in title block; DrawnBy: Sreenivasa; Engineer: Not shown in title block; Organization: Not shown in title block; Address1: Not shown in title block; Address2: Not shown in title block; Address3: Not shown in title block; Address4: Not shown in title block; DocumentNumber: 1; Revision: Use project parameter SCH_Rev; SheetNumber: 10; SheetTotal: 10; PageSetup: Record=PageOptions¦CenterHorizontal=True¦CenterVertical=True¦PrintScale=1.00¦XCorrection=1.00¦YCorrection=1.00¦PrintKind=0¦BorderSize=5000000¦LeftOffset=0¦BottomOffset=0¦Orientation=2¦PaperLength=1000¦PaperWidth=1000¦Scale=100¦PaperSource=15¦PrintQuality=600¦MediaType=1¦DitherType=10¦PaperKind=Letter¦PrintScaleMode=1
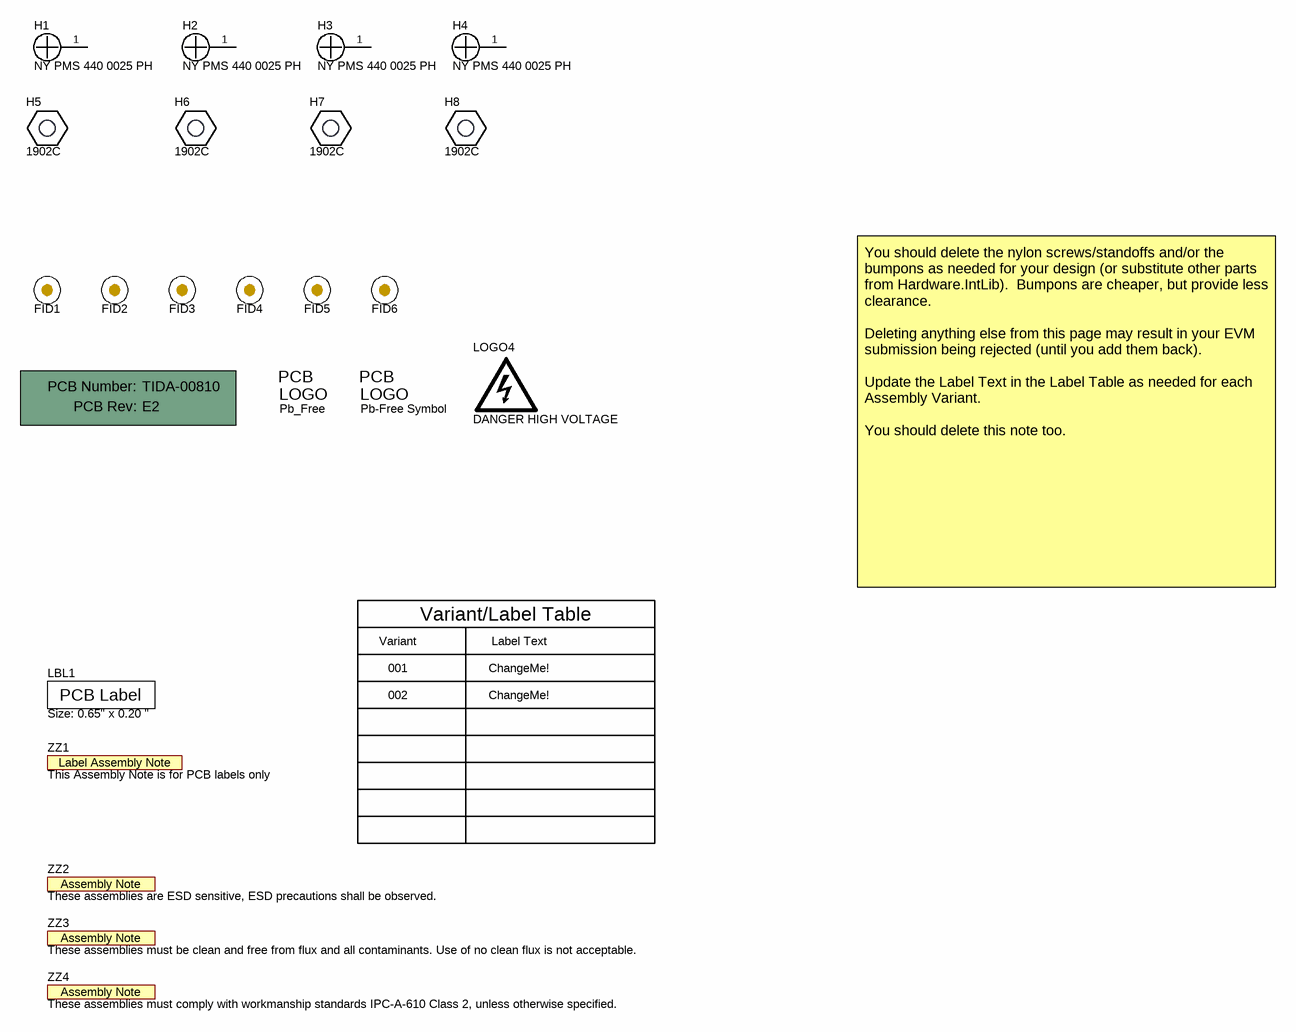
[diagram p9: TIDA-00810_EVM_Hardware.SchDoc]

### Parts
!PCB1  Printed Circuit Board  (value not drawn)  (mechanical)
FID1  Fiducial  [Fiducial10-20]  (value not drawn)
FID2  Fiducial  [Fiducial10-20]  (value not drawn)
FID3  Fiducial  [Fiducial10-20]  (value not drawn)
FID4  Fiducial  [Fiducial10-20]  (value not drawn)
FID5  Fiducial  [Fiducial10-20]  (value not drawn)
FID6  Fiducial  [Fiducial10-20]  (value not drawn)
H1  NY PMS 440 0025 PH  [NY PMS 440 0025 PH]
H2  NY PMS 440 0025 PH  [NY PMS 440 0025 PH]
H3  NY PMS 440 0025 PH  [NY PMS 440 0025 PH]
H4  NY PMS 440 0025 PH  [NY PMS 440 0025 PH]
H5  1902C  [Keystone_1902C]
H6  1902C  [Keystone_1902C]
H7  1902C  [Keystone_1902C]
H8  1902C  [Keystone_1902C]
LBL1  Size: 0.65" x 0.20 "  [Label_650x200]
Logo3  Pb-Free Symbol  [Pb-Free_Overlay_Small]  (no BOM)
LOGO4  DANGER HIGH VOLTAGE  [IEC_HighVoltage_medium]  (no BOM)
Pb_Free  ESD Susceptible  [ESD_Overlay_small]  (value not drawn)  (no BOM)
ZZ1  This Assembly Note is for PCB labels only  [AssemblyNoteLabel]  (no BOM)
ZZ2  These assemblies are ESD sensitive, ESD precautions shall be observed.  [AssemblyNote]  (no BOM)
ZZ3  These assemblies must be clean and free from flux and all contaminants. Use of no clean flux is not acceptable.  [AssemblyNote]  (no BOM)
ZZ4  These assemblies must comply with workmanship standards IPC-A-610 Class 2, unless otherwise specified.  [AssemblyNote]  (no BOM)

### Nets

Not connected (* = marked no-connect by the designer): H1 1; H2 1; H3 1; H4 1

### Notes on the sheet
- Variant
- Variant/Label Table
- Label Text
- You should delete the nylon screws/standoffs and/or the bumpons as needed for your design (or substitute other parts from Hardware.IntLib).  Bumpons are cheaper, but provide less clearance.
  Deleting anything else from this page may result in your EVM submission being rejected (until you add them back).
  Update the Label Text in the Label Table as needed for each Assembly Variant.
  You should delete this note too.
- 001
- 002
- ChangeMe!

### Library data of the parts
!PCB1 = PCB: Manufacturer: Any; PartNumber: TIDA-00810; SymbolCreator: a0412235
FID1-FID6 = Fiducial: Fiducial mark.  There is nothing to buy or mount.; SymbolCreator: codlsc
H1-H4 = NY PMS 440 0025 PH: Machine Screw, Round, #4-40 x 1/4, Nylon, Philips panhead; Manufacturer: B&F Fastener Supply; CompType: Hardware; SymbolCreator: codlsc; U/M: EA
H5-H8 = 1902C: Standoff, Hex, 0.5"L #4-40 Nylon; Manufacturer: Keystone; CompType: Hardware
LBL1 = THT-14-423-10: Thermal Transfer Printable Labels, 0.650" W x 0.200" H - 10,000 per roll; Manufacturer: Brady; SymbolCreator: a0412235; CompType: Label
Logo3 = Pb-Free: SymbolCreator: a0412235
LOGO4 = IEC_HighVoltage: IEC 61010-1 High Voltage Warning; SymbolCreator: a0412235
Pb_Free = ESD_Susceptible: ESD Susceptible Symbol; SymbolCreator: a0412235
ZZ1 = AssemblyNoteLabel: SymbolCreator: a0412235
ZZ2-ZZ4 = AssemblyNote: SymbolCreator: codlsc

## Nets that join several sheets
+5V: TIDA-00810_POWER SUPPLY (D15.1 J12.3 R134.2 R135.2), TIDA-00810_Isolation Amplifier (R182.2 R183.2), TIDA-00810_Reference (6 pins), TIDA-00810_ADC1 (5 pins), TIDA-00810_ADC2 (JP5.1)
AGND: TIDA-00810_POWER SUPPLY (34 pins), TIDA-00810_Isolation Amplifier (10 pins), TIDA-00810_OP-AMP (40 pins), TIDA-00810_Reference (14 pins), TIDA-00810_ADC1 (21 pins), TIDA-00810_ADC2 (17 pins)
AVCC_3.3: TIDA-00810_POWER SUPPLY (5 pins), TIDA-00810_Reference (R124.2 R125.2), TIDA-00810_ADC1 (17 pins), TIDA-00810_ADC2 (8 pins), TIDA-00810_Buffer (L2.1)
AVDD: TIDA-00810_POWER SUPPLY (J12.2), TIDA-00810_OP-AMP (C56.2 C64.2 U10.4 U11.4), TIDA-00810_Reference (R152.2 R155.2 U10.4 U11.4), TIDA-00810_ADC1 (JP2.1), TIDA-00810_ADC2 (JP6.1)
AVSS: TIDA-00810_POWER SUPPLY (J14.2), TIDA-00810_OP-AMP (C59.2 C69.2 U10.11 U11.11), TIDA-00810_Reference (U10.11 U11.11), TIDA-00810_ADC1 (11 pins), TIDA-00810_ADC2 (11 pins)
GND: TIDA-00810_Isolation Amplifier (C45.1 C46.1 U9.4 U9.5), TIDA-00810_ADC1 (13 pins), TIDA-00810_ADC2 (7 pins), TIDA-00810_Buffer (6 pins)
ADC1_CLKIN: TIDA-00810_ADC1 (R21.2), TIDA-00810_Buffer (R47.1)
ADC1_COMP: TIDA-00810_Reference (R119.1 R124.1 U12.4), TIDA-00810_ADC1 (J2.2)
ADC1_REFOUT: TIDA-00810_Reference (R151.1), TIDA-00810_ADC1 (C7.2 C8.2 U2.12)
ADC1_SPI_DONE: TIDA-00810_ADC1 (J2.6 U2.18), TIDA-00810_ADC2 (R38.1)
ADC2_CLKIN: TIDA-00810_ADC2 (R44.2), TIDA-00810_Buffer (R48.1)
ADC2_COMP: TIDA-00810_Reference (R120.2 R125.1 U21.4), TIDA-00810_ADC1 (J2.4)
ADC2_REFOUT: TIDA-00810_Reference (R154.1), TIDA-00810_ADC2 (C26.2 C27.2 U4.12)
ADC2_SPI_DONE: TIDA-00810_ADC1 (J2.1), TIDA-00810_ADC2 (R43.1)
ADC_RESET: TIDA-00810_ADC1 (J2.3 R12.1 R14.1), TIDA-00810_ADC2 (R35.1 R37.1)
ADC_SPI_DRDY: TIDA-00810_ADC1 (J2.5 R19.1 R167.1), TIDA-00810_ADC2 (R42.1)
ADC_SPI_MISO: TIDA-00810_ADC1 (J2.7 R13.1 R18.1), TIDA-00810_ADC2 (R36.1 R41.1)
ADC_SPI_MOSI: TIDA-00810_ADC1 (J2.8 R17.1 R165.1), TIDA-00810_ADC2 (R40.1)
ADC_SPI_SCLK: TIDA-00810_ADC1 (J2.10 R16.1 R166.1), TIDA-00810_ADC2 (R39.1)
CT_1_OUT: TIDA-00810_OP-AMP (C67.1 R96.2), TIDA-00810_ADC1 (R143.2 U2.2)
CT_2_OUT: TIDA-00810_OP-AMP (C68.1 R97.2), TIDA-00810_ADC2 (R149.2 U4.8)
EXT_REF1: TIDA-00810_Reference (R20.1 R127.1), TIDA-00810_ADC1 (R157.1)
EXT_REF2: TIDA-00810_Reference (R128.1 R139.1), TIDA-00810_ADC2 (R161.1)
PD_OUT1: TIDA-00810_OP-AMP (C57.1 R81.2), TIDA-00810_ADC1 (R144.2 U2.4)
PD_OUT2: TIDA-00810_OP-AMP (C58.1 R83.2), TIDA-00810_ADC2 (R150.2 U4.6)
ROGO_1_OUT: TIDA-00810_OP-AMP (C74.1 R111.2 TP4.1), TIDA-00810_ADC1 (R146.2 U2.6)
ROGO_2_OUT: TIDA-00810_OP-AMP (C75.1 R113.2 TP8.1), TIDA-00810_ADC2 (R147.2 U4.4)
SAR2_CS#: TIDA-00810_ADC1 (J1.5), TIDA-00810_ADC2 (R27.2)
SAR_DIN: TIDA-00810_ADC1 (J1.3 R1.2 R163.1), TIDA-00810_ADC2 (R24.2)
SAR_DOUT: TIDA-00810_ADC1 (R2.1 U20.2), TIDA-00810_ADC2 (R25.1)
SAR_SCLK: TIDA-00810_ADC1 (J1.1 R3.2 R140.1), TIDA-00810_ADC2 (R26.2)
VOUT1_N: TIDA-00810_Isolation Amplifier (C110.1 R58.2), TIDA-00810_ADC1 (C105.1 U2.7)
VOUT1_P: TIDA-00810_Isolation Amplifier (C111.1 R57.2), TIDA-00810_ADC1 (C105.2 R145.2 U2.8)
VOUT2_N: TIDA-00810_Isolation Amplifier (C112.1 R69.2), TIDA-00810_ADC2 (C106.1 U4.1)
VOUT2_P: TIDA-00810_Isolation Amplifier (C113.1 R66.2), TIDA-00810_ADC2 (C106.2 R148.2 U4.2)
VREF_ADC1: TIDA-00810_OP-AMP (R130.1 R168.1 R172.1), TIDA-00810_Reference (C76.2 R118.1 R126.2 TP21.1), TIDA-00810_ADC1 (R136.1 R137.1 R138.1)
VREF_ADC2: TIDA-00810_OP-AMP (R131.1 R169.1 R173.1), TIDA-00810_Reference (C77.2 R121.1 R129.2 TP22.1), TIDA-00810_ADC2 (R158.1 R159.1 R160.1)

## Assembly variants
001: not fitted C8 C13 C27 C28 D13 D14 FID1 FID2 FID3 R6 R7 R9 R22 R23 R29 R30 R32 R56 R68 R88 R90 R118 R121 R141 R142 R153 R156 R157 R161 R165 R166 R167 R170 R171 R174 R175 R176 R177 R178 R179 R184 R185 U16 U17 U18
